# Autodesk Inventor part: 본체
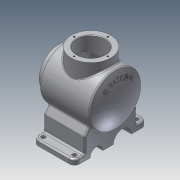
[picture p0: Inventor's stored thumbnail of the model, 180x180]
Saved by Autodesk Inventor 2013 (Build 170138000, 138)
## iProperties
Created: 2018-08
Part Number: 본체
Material: 알루미늄 6061
Document SubType Name: Modeling
Designer: Administrator
Density: 2.71 g/cm^3
Mass: 1886.04 g
Surface Area: 1087.45 cm^2
Volume: 695.956 cm^3
Author: Administrator
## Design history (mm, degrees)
sketch "스케치1"
  geometry: L1 (40, 70)-(-40, 70); L2 (-40, 70)-(-40, -70); L3 (-40, -70)-(40, -70); L4 (40, -70)-(40, 70); L5 (40, 70)-(-40, -70); L6 (-40, 70)-(40, -70); 1 further point
  constraints: 12 end point, 2 midpoint, 2 parallel, 1 horizontal, 1 perpendicular
  dimensions: "d0" = 80 distance of L3.end L2.end; "d1" = 140 distance of L2.end L1.end
extrude "돌출1" new body sketch "스케치1" distance "d2" = 10; taper "d3" = 0 deg
sketch "스케치2"
  geometry: L1 (0, 0)-(0, 82); L2 (48.671, 132)-(-48, 132); L3 (-48, 132)-(-48, 120); L4 (-48, 120)-(-60, 120); L5 (-60, 120)-(-60, 82); L6 (-60, 82)-(60, 82); L7 (-40, 0)-(-40, 10) reference; A1 r 116 centre (-56, 82) between (60, 82) and (48.671, 132)
  constraints: 12 end point, 2 point on circle, 1 centre point, 1 midpoint, 1 parallel, 1 perpendicular, 1 point on line, 1 vertical
  dimensions: "d4" = 82 distance of L1.start L1.end; "d5" = 120 distance of L6.end L5.end; "d6" = 116 radius of A1; "d9" = 12 distance between parallel lines of L3 L5; "d12" = 108 horizontal distance of L2.end L6.end; "d83" = 100 diameter of L2 L6; "d84" = 76 diameter of L4 L6; "d85" = 48 distance from line of L1.end L3
revolve "회전1" sketch "스케치2" stored, may be unused: angle "d13" = 90 deg
sketch "스케치3"
  geometry: L1 (-60, 44)-(-60, 120) reference; L2 (-60, 82)-(60, 82); L3 (42.163, 122)-(-38, 122); L4 (-38, 122)-(-38, 109); L5 (-38, 109)-(-60, 109); A1 r 116 centre (-56, 82) between (48.671, 32) and (48.671, 132) reference; A2 r 106 centre (-56, 82) between (50, 82) and (42.163, 122); 1 further point
  constraints: 8 end point, 3 point on circle, 2 parallel, 2 point on line, 1 centre point, 1 midpoint, 1 perpendicular
  dimensions: "d14" = 10 radial gap between concentric circles of A2 A1; "d15" = 80 diameter of L3 L2; "d16" = 22 distance between parallel lines of L1 L4; "d17" = 54 diameter of L5 L2
revolve "회전2" sketch "스케치3" stored, may be unused: angle "d18" = 90 deg
fillet "모깎기1" dims "d19" = 10
sketch "스케치4"
  geometry: A1 r 10 centre (30, 60) between (40, 60) and (30, 70) reference; A2 r 10 centre (-30, 60) between (-30, 70) and (-40, 60) reference; A3 r 10 centre (-30, -60) between (-40, -60) and (-30, -70) reference; A4 r 10 centre (30, -60) between (30, -70) and (40, -60) reference; 5 further points
  constraints: 4 coincident
hole "구멍1" sketch "스케치4" at (-30, 60), (-30, -60), (30, -60), (30, 60) diameter "d20" = 8; stored, may be unused: countersink angle "d24" = 90 deg, drill point angle "d26" = 118 deg; dims "d21" = 6, "d22" = 4, "d23" = 2, "d25" = 8
sketch "스케치5"
  geometry: L1 (10, 70)-(10, -70) reference; L2 (10, -70)-(0, -70) reference; L3 (0, -70)-(0, 70) reference; L4 (0, 70)-(10, 70) reference; L5 (10, 70)-(52.41, 40.304); L6 (10, 50)-(38.563, 50); L7 (52.41, 40.304)-(38.563, 50); L8 (10, -70)-(52.41, -40.304); L9 (10, -50)-(38.563, -50); L10 (52.41, -40.304)-(38.563, -50); C1 r 40 at (82, 0) reference; A1 r 50 centre (82, 0) between (52.41, 40.304) and (52.41, -40.304) reference; 1 further point
  constraints: 12 end point, 4 point on line, 2 collinear, 2 parallel, 2 point on circle
  dimensions: "d29" = 35 deg angle of L4 L5; "d30" = 20 distance between parallel lines of L6 L4; "d31" = 35 deg angle of L2 L8; "d32" = 20 distance between parallel lines of L2 L9
extrude "돌출2" join sketch "스케치5" stored distance "d33" = 80; taper "d34" = 0 deg
sketch "스케치6"
  geometry: L1 (0, 0)-(120, 0) reference; C1 r 17.5 at (37.5, 0); C2 r 12.5 at (87.5, 0); 1 further point
  constraints: 2 centre point, 2 point on line
  dimensions: "d35" = 35 diameter of C1; "d36" = 25 diameter of C2; "d37" = 22.5 distance of point (60, 0) C1.centre; "d38" = 27.5 distance of C2.centre point (60, 0)
extrude "돌출3" cut sketch "스케치6" stored distance "d39" = 80; taper "d40" = 0 deg
node "작업 평면1"
sketch "스케치7"
  geometry: L1 (48, 50)-(48, -50) reference; L2 (40, -50)-(-40, -50) reference; C1 r 38 at (-2, 0); 1 further point
  constraints: 1 centre point, 1 coincident
  dimensions: "d42" = 76 diameter of C1; "d86" = 50 distance from line of point (-2, 0) L1; "d87" = 50 distance from line of L2 point (-2, 0)
extrude "돌출4" join sketch "스케치7" stored distance "d43" = 80; taper "d44" = 0 deg
sketch "스케치8"
  geometry: C1 r 38 at (0, 0) reference; C2 r 27 at (0, 0)
  constraints: 1 centre point, 1 coincident
  dimensions: "d45" = 54 diameter of C2
extrude "돌출5" cut sketch "스케치8" stored distance "d46" = 80; taper "d47" = 0 deg
sketch "스케치9"
  geometry: L1 (0, 0)-(0, 32.5); C1 r 38 at (0, 0) reference; 1 further point
  constraints: 2 end point, 1 coincident, 1 vertical
  dimensions: "d48" = 32.5 distance of L1.start L1.end
hole "구멍2" sketch "스케치9" at (0, 32.5) diameter "d49" = 3.242; stored, may be unused: countersink angle "d53" = 90 deg, drill point angle "d55" = 118 deg; dims "d50" = 8, "d51" = 4, "d52" = 2, "d54" = 10
sketch "스케치10"
  geometry: L1 (0, 0)-(0, 32.5); C1 r 38 at (0, 0) reference; 2 further points
  constraints: 2 end point, 1 coincident, 1 vertical
  dimensions: "d59" = 32.5 distance of L1.start L1.end
hole "구멍3" sketch "스케치10" at (0, 32.5) diameter "d60" = 3.242; stored, may be unused: countersink angle "d64" = 90 deg, drill point angle "d66" = 118 deg; dims "d61" = 8, "d62" = 4, "d63" = 2, "d65" = 10
chamfer "모따기1" distance "d70" = 1; stored, may be unused: second distance "d71" = 2, angle "d72" = 45 deg
fillet "모깎기2" dims "d73" = 3
fillet "모깎기3" dims "d74" = 3
fillet "모깎기4" dims "d75" = 3
fillet "모깎기5" dims "d76" = 3
fillet "모깎기6" dims "d77" = 3
node "작업 평면3"
sketch "스케치15"
  geometry: C1 r 50 at (82, 0) reference; C2 r 32.5 at (82, 0); 1 further point
  constraints: 1 centre point, 1 coincident, 1 other
  dimensions: "d89" = 65 diameter of C2
feature "엠보싱1" sketch "스케치15" dims "d0" = 80, "d1" = 140, "d90" = 0.5, "d91" = 0
node "솔리드1"
pattern_circular "원형 패턴1" dims angle "d57" = 360 deg
pattern_circular "원형 패턴2" dims angle "d68" = 360 deg
node "절단 모서리 투영1"
other parameters: "d41" = 147
